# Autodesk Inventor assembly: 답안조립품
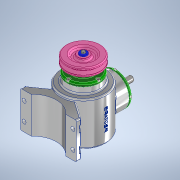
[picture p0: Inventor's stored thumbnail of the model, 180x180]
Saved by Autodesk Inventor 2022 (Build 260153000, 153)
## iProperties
Created: 2023-04
Part Number: 답안조립품
Document SubType Name: Assembly
Designer: ADMIN
Author: ADMIN
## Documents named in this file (17)
- C:\Users\ADMIN\Desktop\730411V1012\답안조립품.iam
- C:\Users\ADMIN\Desktop\730411V1012\본체.ipt
- C:\Users\ADMIN\Desktop\730411V1012\커버.ipt
- C:\Users\ADMIN\Desktop\730411V1012\베어링 6203.ipt
- C:\Users\ADMIN\Desktop\730411V1012\오일실 17 x 32 x 8.ipt
- C:\Users\ADMIN\Desktop\730411V1012\메인 축.ipt
- 메인 축.ipt
- C:\Users\ADMIN\Desktop\730411V1012\키 5 x 5 x 14.ipt
- C:\Users\ADMIN\Desktop\730411V1012\메인 베벨기어.ipt
- C:\Users\ADMIN\Desktop\730411V1012\서브 축.ipt
- 서브 축.ipt
- C:\Users\ADMIN\Desktop\730411V1012\키 4 x 4 x 14.ipt
- C:\Users\ADMIN\Desktop\730411V1012\서브 베벨기어.ipt
- C:\Users\ADMIN\Desktop\730411V1012\V-벨트풀리.ipt
- C:\Users\ADMIN\Desktop\730411V1012\볼트 M4 x 10.ipt
- C:\Users\ADMIN\Desktop\730411V1012\와셔 4 x 16.ipt
- C:\Users\ADMIN\Desktop\730411V1012\육각볼트 M4 x 8.ipt
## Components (1 placed, 1 different names)
1. V-벨트풀리:1
